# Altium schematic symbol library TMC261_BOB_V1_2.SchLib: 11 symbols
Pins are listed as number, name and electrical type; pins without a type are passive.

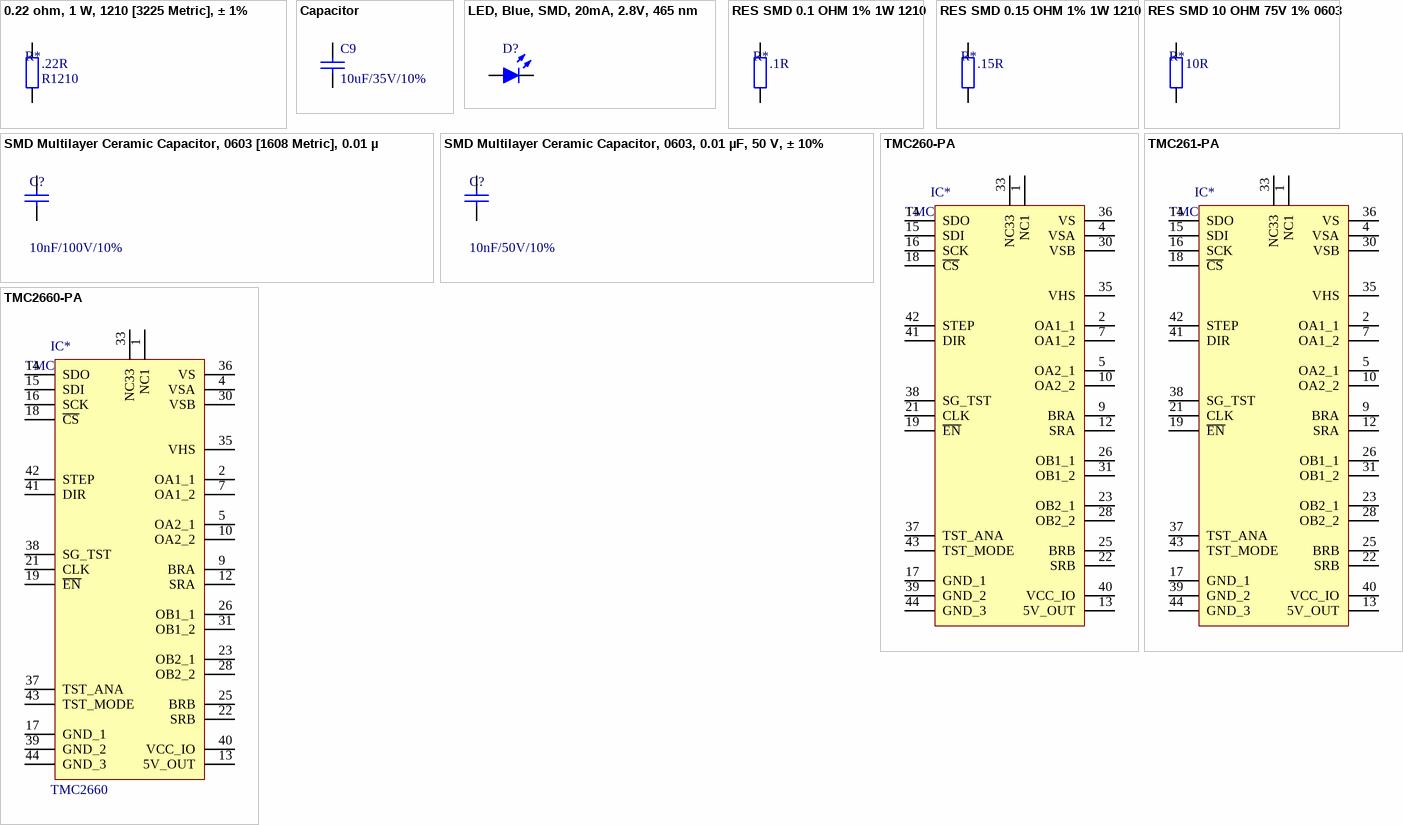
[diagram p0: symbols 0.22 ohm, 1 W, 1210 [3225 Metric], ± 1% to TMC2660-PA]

## 0.22 ohm, 1 W, 1210 [3225 Metric], ± 1%
designator R*, comment Resistance: .22R  (hidden comment: .22R / 1W / 1%)
Current Sense Resistor, 0.22 ohm, 1 W, 1210 [3225 Metric], ± 1%, RCWE Series; MPN: RCWE1210R220FKEA; VoltageRating: 50V; Temp coefficient: *ppm; MF: Vishay
footprint R0402 (0402 resistor)
footprint R0603 (0603 resistor)
footprint R0805 (0805 resistor)
footprint R1206 (1206 resistor)
footprint R2512 (2512 resistor)
footprint R0201 (0201 resistor)
footprint R1210 (1210 resistor)
footprint R1812 (1812 resistor)
footprint R2010 (2010 resistor)
footprint R2512 (2512 resistor)
pins: 1, 2

## Capacitor
designator C9, comment 10uF/35V/10%
Ceramic capacitor; MPN: GRM31CC8YA106KA12L; Type: MLCC; VoltageRating: 35V; ComponentLinknDescription: Datasheet; MF: MURATA; Capacitance: 10uF; Precision: 10%
footprint C0402 (0402 ceramic capacitor)
footprint C0603 (0603 ceramic capacitor)
footprint C0805 (0805 ceramic capacitor)
footprint C1206 (1206 ceramic capacitor)
footprint C1210 (1210 capacitor)
footprint C1812 (1812 capacitor)
pins: 1, 2

## LED, Blue, SMD, 20mA, 2.8V, 465 nm
designator D?  (value not drawn)
MPN: LTST-C191TBKT-5A; MF: Lite-On
footprint LED_0603
footprint LED 3mm (THT LED 3mm, 2.54 pitch)
pins: 1 A, 2 K

## RES SMD 0.1 OHM 1% 1W 1210
designator R*, comment Resistance: .1R  (hidden comment: .1R / 1W / 1%)
0.1 Ohm ±1% 1W Chip Resistor 1210 (3225 Metric) Automotive AEC-Q200, Current Sense, Moisture Resistant Thick Film; MPN: RCWE1210R100FKEA; VoltageRating: 50V; Temp coefficient: *ppm; MF: Vishay
footprint R0402 (0402 resistor)
footprint R0603 (0603 resistor)
footprint R0805 (0805 resistor)
footprint R1206 (1206 resistor)
footprint R2512 (2512 resistor)
footprint R0201 (0201 resistor)
footprint R1210 (1210 resistor)
footprint R1812 (1812 resistor)
footprint R2010 (2010 resistor)
footprint R2512 (2512 resistor)
pins: 1, 2

## RES SMD 0.15 OHM 1% 1W 1210
designator R*, comment Resistance: .15R  (hidden comment: .15R / 1W / 1%)
0.15 Ohm ±1% 1W Chip Resistor 1210 (3225 Metric) Automotive AEC-Q200, Current Sense, Moisture Resistant Thick Film; MPN: RCWE1210R150FKEA; VoltageRating: 50V; Temp coefficient: *ppm; MF: Vishay
footprint R0402 (0402 resistor)
footprint R0603 (0603 resistor)
footprint R0805 (0805 resistor)
footprint R1206 (1206 resistor)
footprint R2512 (2512 resistor)
footprint R0201 (0201 resistor)
footprint R1210 (1210 resistor)
footprint R1812 (1812 resistor)
footprint R2010 (2010 resistor)
footprint R2512 (2512 resistor)
pins: 1, 2

## RES SMD 10 OHM 75V 1% 0603
designator R*, comment Resistance: 10R  (hidden comment: 10R / 100mW / 1%)
0.1 Ohm ±1% 1W Chip Resistor 1210 (3225 Metric) Automotive AEC-Q200, Current Sense, Moisture Resistant Thick Film; MPN: MCMR06X10R0FTL; VoltageRating: 75V; Temp coefficient: *ppm; MF: MULTICOMP
footprint R0402 (0402 resistor)
footprint R0603 (0603 resistor)
footprint R0805 (0805 resistor)
footprint R1206 (1206 resistor)
footprint R2512 (2512 resistor)
footprint R0201 (0201 resistor)
footprint R1210 (1210 resistor)
footprint R1812 (1812 resistor)
footprint R2010 (2010 resistor)
footprint R2512 (2512 resistor)
pins: 1, 2

## SMD Multilayer Ceramic Capacitor, 0603 [1608 Metric], 0.01 µF, 100 V, ± 10%, X7R, MC Series
designator C?, comment 10nF/100V/10%
Ceramic capacitor; MPN: MC0603B103K101CT; Type: MLCC; VoltageRating: 100V; MF: MULTICOMP; Precision: 10%; Capacitance: 10nF
footprint C0402 (0402 ceramic capacitor)
footprint C0603 (0603 ceramic capacitor)
footprint C0805 (0805 ceramic capacitor)
footprint C1206 (1206 ceramic capacitor)
footprint C1210 (1210 capacitor)
footprint C1812 (1812 capacitor)
footprint C 8.3x8.3mm (Aluminum Electrolytic Capacitor, Body 8.30x8.30x11.70mm, IPC Low Density)
pins: 1, 2

## SMD Multilayer Ceramic Capacitor, 0603, 0.01 µF, 50 V, ± 10%
designator C?, comment 10nF/50V/10%
Ceramic capacitor; MPN: MC0603B103K500C; Type: MLCC; VoltageRating: 50V; MF: MULTICOMP; Precision: 10%; Capacitance: 10nF
footprint C0402 (0402 ceramic capacitor)
footprint C0603 (0603 ceramic capacitor)
footprint C0805 (0805 ceramic capacitor)
footprint C1206 (1206 ceramic capacitor)
footprint C1210 (1210 capacitor)
footprint C1812 (1812 capacitor)
footprint C 8.3x8.3mm (Aluminum Electrolytic Capacitor, Body 8.30x8.30x11.70mm, IPC Low Density)
pins: 1, 2

## TMC260-PA
designator IC*, comment value TMC260-PA  (hidden comment: TMC260)
coolStep™ driver with Step/Dir Interface and SPI, up to 30V,  internal MOSFET for up to 4 A, PQFP-44; Manufacturer: TRINAMIC; Ordercode - Distri#1: 1460-1042-ND; Geometry.Height: 1,6mm
footprint TMC26x_PQFP44_0.8_10X10_TMC236
pins: 1 NC1, 2 OA1_1, 4 VSA, 5 OA2_1, 7 OA1_2, 9 BRA, 10 OA2_2, 12 SRA, 13 5V_OUT, 14 SDO, 15 SDI, 16 SCK, 17 GND_1, 18 ~{CS}, 19 ~{EN}, 21 CLK, 22 SRB, 23 OB2_1, 25 BRB, 26 OB1_1, 28 OB2_2, 30 VSB, 31 OB1_2, 33 NC33, 35 VHS (power), 36 VS (power), 37 TST_ANA, 38 SG_TST, 39 GND_2, 40 VCC_IO (power), 41 DIR, 42 STEP, 43 TST_MODE, 44 GND_3

## TMC261-PA
designator IC*, comment value TMC261-PA  (hidden comment: TMC261)
coolStep™ driver with Step/Dir Interface and SPI, up to 30V,  internal MOSFET for up to 4 A, PQFP-44; Manufacturer: TRINAMIC; Ordercode - Distri#1: 1460-1043-ND; Geometry.Height: 1,6mm
footprint TMC26x_PQFP44_0.8_10X10_TMC236
pins: 1 NC1, 2 OA1_1, 4 VSA, 5 OA2_1, 7 OA1_2, 9 BRA, 10 OA2_2, 12 SRA, 13 5V_OUT, 14 SDO, 15 SDI, 16 SCK, 17 GND_1, 18 ~{CS}, 19 ~{EN}, 21 CLK, 22 SRB, 23 OB2_1, 25 BRB, 26 OB1_1, 28 OB2_2, 30 VSB, 31 OB1_2, 33 NC33, 35 VHS (power), 36 VS (power), 37 TST_ANA, 38 SG_TST, 39 GND_2, 40 VCC_IO (power), 41 DIR, 42 STEP, 43 TST_MODE, 44 GND_3

## TMC2660-PA
designator IC*, comment TMC2660  value TMC2660-PA
coolStep™ driver with Step/Dir Interface and SPI, up to 30V,  internal MOSFET for up to 4 A, PQFP-44; Manufacturer: TRINAMIC; Ordercode - Distri#1: 1460-1059-ND; Geometry.Height: 1,6mm
footprint TMC26x_PQFP44_0.8_10X10_TMC236
pins: 1 NC1, 2 OA1_1, 4 VSA, 5 OA2_1, 7 OA1_2, 9 BRA, 10 OA2_2, 12 SRA, 13 5V_OUT, 14 SDO, 15 SDI, 16 SCK, 17 GND_1, 18 ~{CS}, 19 ~{EN}, 21 CLK, 22 SRB, 23 OB2_1, 25 BRB, 26 OB1_1, 28 OB2_2, 30 VSB, 31 OB1_2, 33 NC33, 35 VHS (power), 36 VS (power), 37 TST_ANA, 38 SG_TST, 39 GND_2, 40 VCC_IO (power), 41 DIR, 42 STEP, 43 TST_MODE, 44 GND_3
